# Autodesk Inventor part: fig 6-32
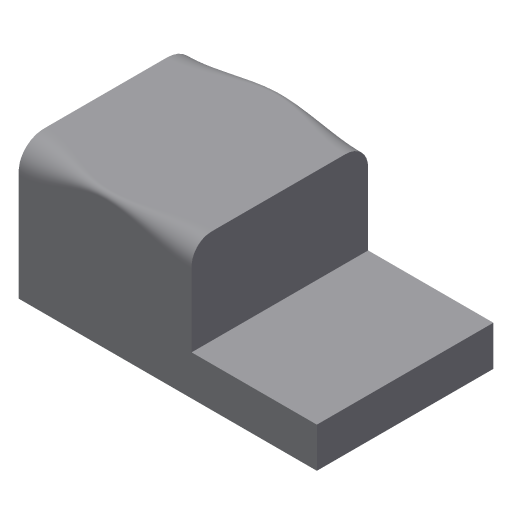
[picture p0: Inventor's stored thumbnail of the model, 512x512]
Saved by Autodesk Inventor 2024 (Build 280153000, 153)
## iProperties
Created: 2004-05
Part Number: fig 6-32
Document SubType Name: Modeling
Designer: CADCIM Technologies
Manufacturer: Standard
Standards Organization: Custom
Density: 1 g/cm^3
Material: Generic
Appearance: Default
Author: CADCIM Technologies
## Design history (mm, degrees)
sketch "Sketch2"
  geometry: L1 (0.098, 47.711)-(0.098, 0.049); L2 (0.098, 0.049)-(-105.483, 0.049); L3 (-105.483, 0.049)-(-105.483, 14.192); L4 (-105.483, 14.192)-(-61.139, 14.192); L5 (-61.139, 14.192)-(-61.139, 47.711); L6 (-61.139, 47.711)-(0.098, 47.711)
  constraints: 12 end point, 3 parallel, 2 perpendicular, 1 vertical
extrude "Extrusion1" new body sketch "Sketch2" stored distance "d0" = 62.5; taper "d1" = 0 deg
fillet "Fillet9" dims "d61" = 10, "d62" = 8, "d63" = 2, "d64" = 5
fillet "Fillet10" dims "d65" = 8, "d66" = 10, "d67" = 2, "d68" = 5
body "Solid1"
node "Sketch1"
